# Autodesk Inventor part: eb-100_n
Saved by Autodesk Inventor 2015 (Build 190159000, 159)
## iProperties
Created: 2020-07
Part Number: eb-100_n
Checked By: TraceParts S.A.
Material: Generic
Catalog Web Link: www.traceparts.com
Document SubType Name: Modeling
Designer: TraceParts
Density: 1 g/cm^3
Appearance: Default
Company: TraceParts S.A.
Author: TraceParts
REFERENCE: EB-100 N
DESIGN: EB-100 N
SUPPLIER: Soler & Palau
TraceParts.PartNumber: 10-04022019-080764
TraceParts.PartTitle: EB
TraceParts.InstanceId: 10-04022019-0807648YGUMNIPPFUIDPQ0VVNCLVJ2J
TraceParts.PartStatus: Published
TraceParts.PartVersion: 1.0.1
TRACEPARTS: TRACEPARTS
TraceParts.PartLanguage: en
TraceParts.ClassPath: SOLER_PALAU:10-04022019-080764
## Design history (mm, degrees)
feature "eb-100_n"
body "Solid1"
